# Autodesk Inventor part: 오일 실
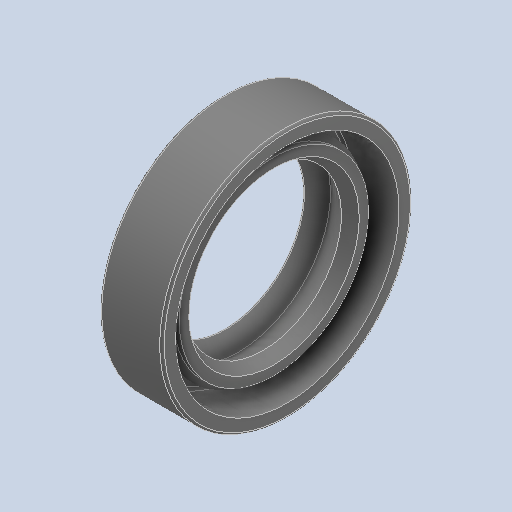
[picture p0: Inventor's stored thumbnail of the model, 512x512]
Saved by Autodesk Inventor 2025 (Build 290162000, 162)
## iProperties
Created: 2024-08
Part Number: 오일 실
Material: 고무
Description: 오일-실
Document SubType Name: Modeling
Designer: hsj03
Density: 0.93 g/cm^3
Appearance: 기본값
Author: jhkim
Sending System: Autodesk Inventor 2025
Preprocessor: ST-DEVELOPER v20
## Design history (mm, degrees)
feature "Solid1"
node "솔리드1"
